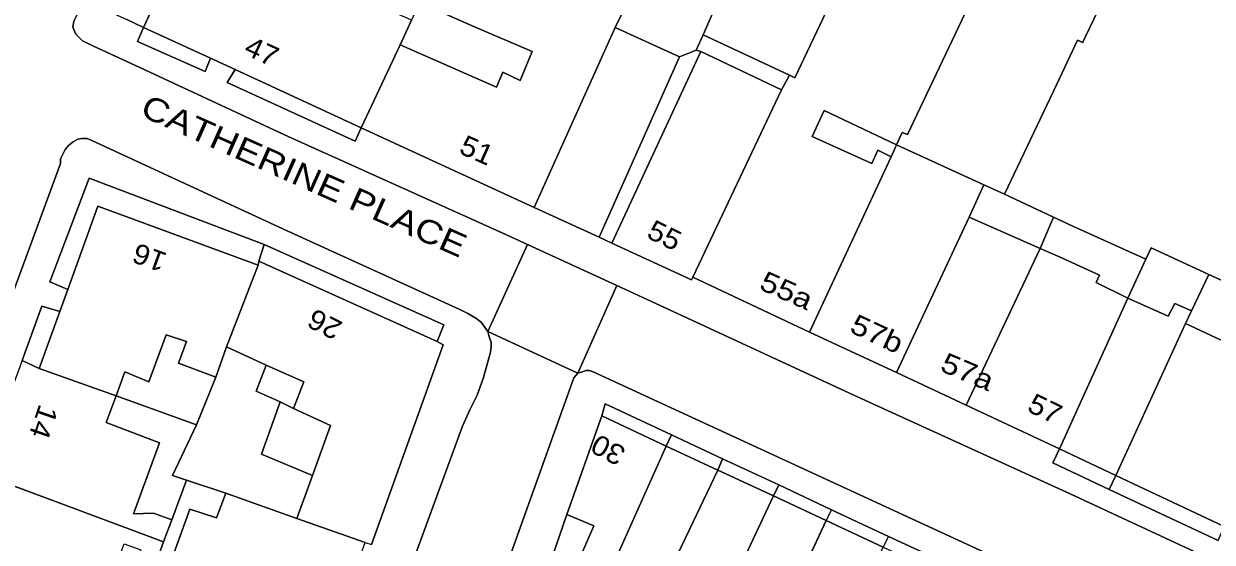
# Model space of a CAD drawing. Extents: x 528790 to 529292, y 179350 to 179856.
# Drawn here: x 529148.9 to 529237.6, y 179419.8 to 179458.5 of the extents above; entities that cross this region are included whole.
import ezdxf

# ---------------------------------------------------------------- set-up
doc = ezdxf.new("R2010")
doc.units = 0
doc.header["$LTSCALE"] = 0.6
doc.layers.add('1', color=7, linetype='Continuous', lineweight=13)
doc.layers.add('2', color=7, linetype='Continuous', lineweight=13)
doc.layers.add('5', color=7, linetype='Continuous')

msp = doc.modelspace()

# ---------------------------------------------------------------- linework, layer by layer
at = {"layer": '1'}
for points in [[(529203.704, 179467.191), (529210.6, 179482.95), (529209.35, 179483.45), (529205.4, 179484.95), (529199.95, 179473.2), (529198.94, 179470.979), (529201.672, 179469.755), (529199.962, 179465.94), (529197.23, 179467.164), (529196.947, 179466.532), (529195.7, 179463.85), (529193, 179458.25), (529197.8, 179456.05), (529199.05, 179456.55), (529199.55, 179457.7), (529201.924, 179463.125)], [(529218.5, 179480), (529210.6, 179482.95), (529203.704, 179467.191), (529209.252, 179464.762), (529207.472, 179460.696), (529201.924, 179463.125), (529199.55, 179457.7), (529206, 179454.7), (529206.4, 179454.5)], [(529223.465, 179467.493), (529224.55, 179469.75), (529227.4, 179475.9), (529221.2, 179478.75), (529218.5, 179480), (529206.4, 179454.5), (529206, 179454.7), (529205.4, 179453.6), (529198.8, 179439.6), (529207.5, 179435.5), (529213.6, 179448.6), (529212.6, 179449.1), (529212.15, 179448.1), (529207.7, 179450.1), (529208.6, 179452.05), (529214, 179449.5), (529214.4, 179450.4), (529214.8, 179450.25), (529219.8, 179460.8), (529220.2, 179460.7)], [(529157.8, 179458.25), (529161.45, 179466.1), (529164.55, 179472.75), (529165.2, 179474.3), (529160.8, 179476.3), (529160.65, 179475.95), (529155.75, 179465.25), (529153.4, 179460.25), (529156.55, 179458.85)], [(529229.655, 179460.856), (529234.9, 179472.4), (529232.55, 179473.5), (529229.4, 179474.9), (529227.4, 179475.9), (529224.55, 179469.75), (529223.465, 179467.493), (529220.2, 179460.7), (529219.8, 179460.8), (529214.8, 179450.25), (529214.4, 179450.4), (529214, 179449.5), (529220.5, 179446.5), (529222.05, 179445.8), (529225.703, 179453.506), (529226.15, 179454.45), (529227.5, 179457.3), (529227.887, 179457.117), (529227.929, 179457.205), (529228.098, 179457.563)], [(529195.7, 179463.85), (529191.02, 179466.027), (529189.25, 179466.85), (529187.829, 179463.891), (529187.184, 179462.499), (529187, 179462.1), (529180.6, 179465.05), (529178.371, 179460.076), (529180.398, 179459.204), (529182.5, 179458.3), (529186.8, 179456.45), (529185.9, 179454.3), (529184.6, 179454.9), (529184.15, 179453.8), (529179, 179456.05), (529176.939, 179456.951), (529174.05, 179450.75), (529186.95, 179444.8), (529193, 179458.25)], [(529177.8, 179458.8), (529161.45, 179466.1), (529157.8, 179458.25), (529162.8, 179455.95), (529164.65, 179455.1), (529174.05, 179450.75), (529176.939, 179456.951)], [(529186.8, 179456.45), (529182.5, 179458.3), (529180.398, 179459.204), (529178.371, 179460.076), (529177.8, 179458.8), (529176.939, 179456.951), (529179, 179456.05), (529184.15, 179453.8), (529184.6, 179454.9), (529185.9, 179454.3)], [(529157.8, 179458.25), (529157.35, 179457.2), (529162.4, 179454.95), (529162.8, 179455.95)], [(529191.8, 179442.6), (529197.8, 179456.05), (529193, 179458.25), (529186.95, 179444.8)], [(529205.4, 179453.6), (529206, 179454.7), (529199.55, 179457.7), (529199.05, 179456.55), (529199.4, 179456.45)], [(529199.4, 179456.45), (529199.05, 179456.55), (529197.8, 179456.05), (529191.8, 179442.6), (529192.75, 179442.15)], [(529199.4, 179456.45), (529192.75, 179442.15), (529198.7, 179439.4), (529198.8, 179439.6), (529205.4, 179453.6)], [(529164.65, 179455.1), (529164.05, 179454.15), (529173.6, 179449.75), (529174.05, 179450.75)], [(529213.6, 179448.6), (529214, 179449.5), (529208.6, 179452.05), (529207.7, 179450.1), (529212.15, 179448.1), (529212.6, 179449.1)], [(529207.5, 179435.5), (529214, 179432.5), (529219.4, 179444.1), (529220.5, 179446.5), (529214, 179449.5), (529213.6, 179448.6)], [(529166.35, 179440.5), (529166.4, 179440.8), (529166.8, 179442.05), (529153.75, 179447), (529150.8, 179439.25), (529152.15, 179438.7), (529154.4, 179444.9)], [(529224.7, 179441.75), (529225.7, 179444.1), (529222.05, 179445.8), (529220.5, 179446.5), (529219.4, 179444.1)], [(529152.15, 179438.7), (529151.55, 179437.05), (529150, 179432.8), (529155.75, 179430.75), (529156.4, 179432.55), (529158.2, 179431.8), (529159.5, 179435.3), (529161, 179434.8), (529160.4, 179433.2), (529163.2, 179432.15), (529164, 179434.4), (529166.35, 179440.5), (529154.4, 179444.9)], [(529219.4, 179444.1), (529214, 179432.5), (529219.2, 179430.05), (529224.7, 179441.75)], [(529232.6, 179440.95), (529227.2, 179443.4), (529225.7, 179444.1), (529224.7, 179441.75), (529226.2, 179441.1), (529229.15, 179439.75), (529228.9, 179439.2), (529231.25, 179438.05)], [(529166.8, 179442.05), (529166.4, 179440.8), (529179.7, 179434.8), (529180.2, 179436.05)], [(529186.46, 179442.05), (529183.5, 179435.55), (529190.2, 179432.45), (529193.12, 179438.98)], [(529231.25, 179438.05), (529228.9, 179439.2), (529229.15, 179439.75), (529226.2, 179441.1), (529224.7, 179441.75), (529219.2, 179430.05), (529226.15, 179426.8)], [(529237.3, 179439.8), (529233, 179441.8), (529232.6, 179440.95), (529231.25, 179438.05), (529234.25, 179436.7), (529234.75, 179437.65), (529236, 179437.1)], [(529174.35, 179419.8), (529174.8, 179419.65), (529180.15, 179434.55), (529179.7, 179434.8), (529166.4, 179440.8), (529166.35, 179440.5), (529164, 179434.4), (529166.95, 179433.05), (529169.75, 179431.8), (529169, 179429.8), (529171.75, 179428.55), (529170.4, 179424.8), (529169.25, 179421.6)], [(529245.4, 179436.1), (529237.3, 179439.8), (529236, 179437.1), (529235.55, 179436.15), (529241.25, 179433.5), (529243.663, 179432.378)], [(529190.2, 179432.45), (529190.55, 179432.55), (529190.8, 179432.65), (529191.05, 179432.65), (529191.35, 179432.55), (529242.05, 179409.15), (529242.35, 179408.85), (529242.6, 179408.15), (529250, 179413.05), (529240.8, 179417), (529226.95, 179423.45), (529210.8, 179430.8), (529195.7, 179437.8), (529193.12, 179438.98)], [(529226.15, 179426.8), (529230.35, 179424.8), (529235.55, 179436.15), (529236, 179437.1), (529234.75, 179437.65), (529234.25, 179436.7), (529231.25, 179438.05)], [(529150, 179432.8), (529151.55, 179437.05), (529150.2, 179437.45), (529148.75, 179433.4)], [(529242.6, 179430.1), (529243.663, 179432.378), (529241.25, 179433.5), (529235.55, 179436.15), (529230.35, 179424.8), (529238.45, 179421)], [(529161.75, 179428.6), (529163.2, 179432.15), (529160.4, 179433.2), (529161, 179434.8), (529159.5, 179435.3), (529158.2, 179431.8), (529156.4, 179432.55), (529155.75, 179430.75)], [(529163.2, 179432.15), (529161.75, 179428.6), (529159.95, 179424.8), (529161, 179424.45), (529163.95, 179423.5), (529169.25, 179421.6), (529170.4, 179424.8), (529166.6, 179426.4), (529168, 179430.3), (529166.2, 179431.1), (529166.95, 179433.05), (529164, 179434.4)], [(529159.9, 179421.5), (529158.55, 179422), (529157.05, 179421.95), (529159, 179427.25), (529155, 179428.75), (529155.75, 179430.75), (529150, 179432.8), (529148.75, 179433.4), (529145.6, 179424.95), (529159.3, 179419.85)], [(529168, 179430.3), (529169, 179429.8), (529169.75, 179431.8), (529166.95, 179433.05), (529166.2, 179431.1)], [(529159.9, 179421.5), (529161, 179424.45), (529159.95, 179424.8), (529161.75, 179428.6), (529155.75, 179430.75), (529155, 179428.75), (529159, 179427.25), (529157.05, 179421.95), (529158.55, 179422)], [(529169, 179429.8), (529168, 179430.3), (529166.6, 179426.4), (529170.4, 179424.8), (529171.75, 179428.55)], [(529196.8, 179427), (529197.2, 179427.85), (529192.25, 179430.15), (529192, 179429.25)], [(529192.8, 179418.05), (529196.8, 179427), (529192, 179429.25), (529189.4, 179421.9), (529191.4, 179421.05), (529190.55, 179419.1)], [(529201, 179426.05), (529197.2, 179427.85), (529196.8, 179427), (529200.65, 179425.2)], [(529192.6, 179417.75), (529196.35, 179416.05), (529197.75, 179419.1), (529200.65, 179425.2), (529196.8, 179427), (529192.8, 179418.05)], [(529200.65, 179425.2), (529204.8, 179423.3), (529205.2, 179424.1), (529201, 179426.05)], [(529230.35, 179424.8), (529226.15, 179426.8), (529225.65, 179425.75), (529229.85, 179423.75)], [(529201.95, 179417.2), (529204.8, 179423.3), (529200.65, 179425.2), (529197.75, 179419.1)], [(529154, 179405.35), (529154.8, 179407.55), (529152.2, 179408.5), (529156.35, 179419.7), (529157.6, 179419.25), (529157.4, 179418.65), (529158.7, 179418.2), (529159.3, 179419.85), (529145.6, 179424.95), (529144.8, 179422.75), (529144.15, 179421), (529142.4, 179416.4), (529143.2, 179416.1), (529140.9, 179409.8), (529151.2, 179405.95), (529153.9, 179405)], [(529158.7, 179418.2), (529157.9, 179416.1), (529159, 179415.75), (529160.8, 179415.1), (529161.6, 179417.1), (529160.2, 179417.55), (529160.6, 179418.5), (529159.95, 179418.7), (529161.25, 179422.3), (529163.25, 179421.65), (529163.95, 179423.5), (529161, 179424.45), (529159.9, 179421.5), (529159.3, 179419.85)], [(529238, 179419.95), (529238.45, 179421), (529230.35, 179424.8), (529229.85, 179423.75)], [(529172.15, 179413.75), (529174.35, 179419.8), (529169.25, 179421.6), (529163.95, 179423.5), (529163.25, 179421.65), (529161.25, 179422.3), (529159.95, 179418.7), (529160.6, 179418.5), (529160.2, 179417.55), (529161.6, 179417.1), (529160.8, 179415.1), (529171.2, 179411.3)], [(529209.15, 179422.25), (529205.2, 179424.1), (529204.8, 179423.3), (529208.75, 179421.45)], [(529208.75, 179421.45), (529204.8, 179423.3), (529201.95, 179417.2), (529200.4, 179413.7), (529202.75, 179412.65), (529201.4, 179409.8), (529203, 179409.1), (529204.2, 179411.7)], [(529191.45, 179415.1), (529192.6, 179417.75), (529192.8, 179418.05), (529190.55, 179419.1), (529191.4, 179421.05), (529189.4, 179421.9), (529187.55, 179416.55), (529187, 179415.05), (529190.8, 179413.7)], [(529208.75, 179421.45), (529213, 179419.45), (529213.4, 179420.25), (529209.15, 179422.25)], [(529204.2, 179411.7), (529208.6, 179409.7), (529213, 179419.45), (529208.75, 179421.45)], [(529213.4, 179420.25), (529213, 179419.45), (529217.15, 179417.55), (529217.5, 179418.35)]]:
    msp.add_lwpolyline(points, close=True, dxfattribs=at)
for points in [[(529229.655, 179460.856), (529228.098, 179457.563), (529227.929, 179457.205), (529227.887, 179457.117), (529227.5, 179457.3), (529226.15, 179454.45), (529225.703, 179453.506), (529222.05, 179445.8), (529225.7, 179444.1), (529227.2, 179443.4), (529232.6, 179440.95), (529233, 179441.8), (529237.3, 179439.8), (529245.4, 179436.1), (529246.7, 179435.5), (529249.795, 179441.859), (529253.448, 179449.363), (529254.218, 179450.942), (529255.002, 179452.549), (529259, 179460.75)], [(529129.6, 179388.25), (529151.6, 179448.1), (529151.6, 179448.45), (529151.95, 179449.15), (529152.2, 179449.45), (529152.55, 179449.7), (529152.9, 179449.9), (529153.2, 179449.95), (529153.6, 179449.95), (529153.95, 179449.8), (529168.25, 179443.2), (529181.4, 179437.2), (529182, 179436.9), (529182.6, 179436.55), (529183, 179436.25), (529183.5, 179435.55), (529186.46, 179442.05), (529184.6, 179442.9), (529168.6, 179450.1), (529157.2, 179455.4), (529154.075, 179456.846), (529153.247, 179457.24), (529152.737, 179457.756), (529152.53, 179458.27), (529152.592, 179458.708)], [(529152.592, 179458.708), (529152.53, 179458.27), (529152.737, 179457.756), (529153.247, 179457.24), (529154.075, 179456.846), (529157.2, 179455.4), (529168.6, 179450.1), (529184.6, 179442.9), (529186.46, 179442.05), (529193.12, 179438.98), (529195.7, 179437.8), (529210.8, 179430.8), (529226.95, 179423.45), (529240.8, 179417)], [(529238, 179419.95), (529229.85, 179423.75), (529225.65, 179425.75), (529226.15, 179426.8), (529219.2, 179430.05), (529214, 179432.5), (529207.5, 179435.5), (529198.8, 179439.6), (529198.7, 179439.4), (529192.75, 179442.15), (529191.8, 179442.6), (529186.95, 179444.8), (529174.05, 179450.75), (529173.6, 179449.75), (529164.05, 179454.15), (529164.65, 179455.1), (529162.8, 179455.95), (529162.4, 179454.95), (529157.35, 179457.2), (529157.8, 179458.25), (529156.55, 179458.85)], [(529176.4, 179414.3), (529181.6, 179428.5), (529182.15, 179429.7), (529182.7, 179430.8), (529183.15, 179432.05), (529183.5, 179433.3), (529183.7, 179434), (529183.75, 179434.4), (529183.75, 179434.75), (529183.6, 179435.15), (529183.5, 179435.55), (529183, 179436.25), (529182.6, 179436.55), (529182, 179436.9), (529181.4, 179437.2), (529168.25, 179443.2), (529153.95, 179449.8), (529153.6, 179449.95), (529153.2, 179449.95), (529152.9, 179449.9), (529152.55, 179449.7), (529152.2, 179449.45), (529151.95, 179449.15), (529151.6, 179448.45), (529151.6, 179448.1), (529129.6, 179388.25)], [(529148.75, 179433.4), (529150.2, 179437.45), (529151.55, 179437.05), (529152.15, 179438.7), (529150.8, 179439.25), (529153.75, 179447), (529166.8, 179442.05), (529180.2, 179436.05), (529179.7, 179434.8), (529180.15, 179434.55), (529174.8, 179419.65)], [(529169.205, 179374.273), (529189.9, 179432.1), (529190.2, 179432.45), (529183.5, 179435.55), (529183.6, 179435.15), (529183.75, 179434.75), (529183.75, 179434.4), (529183.7, 179434), (529183.5, 179433.3), (529183.15, 179432.05), (529182.7, 179430.8), (529182.15, 179429.7), (529181.6, 179428.5), (529176.4, 179414.3)], [(529242.05, 179409.15), (529191.35, 179432.55), (529191.05, 179432.65), (529190.8, 179432.65), (529190.55, 179432.55), (529190.2, 179432.45), (529189.9, 179432.1), (529169.205, 179374.273)], [(529187.55, 179416.55), (529189.4, 179421.9), (529192, 179429.25), (529192.25, 179430.15), (529197.2, 179427.85), (529201, 179426.05), (529205.2, 179424.1), (529209.15, 179422.25), (529213.4, 179420.25), (529217.5, 179418.35)]]:
    msp.add_lwpolyline(points, dxfattribs=at)
at = {"layer": '2'}
for p, q in [((529161.45, 179466.1), (529157.8, 179458.25)), ((529195.7, 179463.85), (529193, 179458.25)), ((529201.924, 179463.125), (529199.55, 179457.7)), ((529157.8, 179458.25), (529162.8, 179455.95)), ((529177.8, 179458.8), (529176.939, 179456.951)), ((529186.95, 179444.8), (529193, 179458.25)), ((529193, 179458.25), (529197.8, 179456.05)), ((529199.55, 179457.7), (529199.05, 179456.55)), ((529206, 179454.7), (529199.55, 179457.7)), ((529174.05, 179450.75), (529176.939, 179456.951)), ((529192.75, 179442.15), (529199.4, 179456.45)), ((529199.05, 179456.55), (529197.8, 179456.05)), ((529199.05, 179456.55), (529199.4, 179456.45)), ((529199.4, 179456.45), (529205.4, 179453.6)), ((529162.8, 179455.95), (529164.65, 179455.1)), ((529197.8, 179456.05), (529191.8, 179442.6)), ((529164.65, 179455.1), (529174.05, 179450.75)), ((529205.4, 179453.6), (529206, 179454.7)), ((529205.4, 179453.6), (529198.8, 179439.6)), ((529174.05, 179450.75), (529186.95, 179444.8)), ((529213.6, 179448.6), (529214, 179449.5)), ((529214, 179449.5), (529220.5, 179446.5)), ((529207.5, 179435.5), (529213.6, 179448.6)), ((529220.5, 179446.5), (529219.4, 179444.1)), ((529222.05, 179445.8), (529220.5, 179446.5)), ((529222.05, 179445.8), (529225.7, 179444.1)), ((529186.95, 179444.8), (529191.8, 179442.6)), ((529219.4, 179444.1), (529214, 179432.5)), ((529219.4, 179444.1), (529224.7, 179441.75)), ((529224.7, 179441.75), (529225.7, 179444.1)), ((529166.8, 179442.05), (529166.4, 179440.8)), ((529183.5, 179435.55), (529186.46, 179442.05)), ((529193.12, 179438.98), (529186.46, 179442.05)), ((529191.8, 179442.6), (529192.75, 179442.15)), ((529224.7, 179441.75), (529219.2, 179430.05)), ((529166.35, 179440.5), (529164, 179434.4)), ((529166.35, 179440.5), (529166.4, 179440.8)), ((529166.4, 179440.8), (529179.7, 179434.8)), ((529232.6, 179440.95), (529231.25, 179438.05)), ((529198.8, 179439.6), (529207.5, 179435.5)), ((529236, 179437.1), (529237.3, 179439.8)), ((529237.3, 179439.8), (529245.4, 179436.1)), ((529151.55, 179437.05), (529152.15, 179438.7)), ((529190.2, 179432.45), (529193.12, 179438.98)), ((529231.25, 179438.05), (529226.15, 179426.8)), ((529150, 179432.8), (529151.55, 179437.05)), ((529236, 179437.1), (529235.55, 179436.15)), ((529235.55, 179436.15), (529230.35, 179424.8)), ((529183.5, 179435.55), (529190.2, 179432.45)), ((529207.5, 179435.5), (529214, 179432.5)), ((529164, 179434.4), (529163.2, 179432.15)), ((529166.95, 179433.05), (529164, 179434.4)), ((529148.75, 179433.4), (529150, 179432.8)), ((529150, 179432.8), (529155.75, 179430.75)), ((529214, 179432.5), (529219.2, 179430.05)), ((529163.2, 179432.15), (529161.75, 179428.6)), ((529155.75, 179430.75), (529161.75, 179428.6)), ((529168, 179430.3), (529169, 179429.8)), ((529219.2, 179430.05), (529226.15, 179426.8)), ((529192, 179429.25), (529189.4, 179421.9)), ((529192, 179429.25), (529196.8, 179427)), ((529197.2, 179427.85), (529196.8, 179427)), ((529201, 179426.05), (529197.2, 179427.85)), ((529196.8, 179427), (529192.8, 179418.05)), ((529196.8, 179427), (529200.65, 179425.2)), ((529201, 179426.05), (529200.65, 179425.2)), ((529205.2, 179424.1), (529201, 179426.05)), ((529226.15, 179426.8), (529230.35, 179424.8)), ((529200.65, 179425.2), (529197.75, 179419.1)), ((529200.65, 179425.2), (529204.8, 179423.3)), ((529159.3, 179419.85), (529145.6, 179424.95)), ((529161, 179424.45), (529159.9, 179421.5)), ((529161, 179424.45), (529163.95, 179423.5)), ((529169.25, 179421.6), (529170.4, 179424.8)), ((529230.35, 179424.8), (529229.85, 179423.75)), ((529230.35, 179424.8), (529238.45, 179421)), ((529169.25, 179421.6), (529163.95, 179423.5)), ((529205.2, 179424.1), (529204.8, 179423.3)), ((529209.15, 179422.25), (529205.2, 179424.1)), ((529229.85, 179423.75), (529238, 179419.95)), ((529204.8, 179423.3), (529201.95, 179417.2)), ((529204.8, 179423.3), (529208.75, 179421.45)), ((529209.15, 179422.25), (529208.75, 179421.45)), ((529213.4, 179420.25), (529209.15, 179422.25)), ((529159.9, 179421.5), (529159.3, 179419.85)), ((529174.35, 179419.8), (529169.25, 179421.6)), ((529208.75, 179421.45), (529204.2, 179411.7)), ((529208.75, 179421.45), (529213, 179419.45)), ((529159.3, 179419.85), (529158.7, 179418.2)), ((529213.4, 179420.25), (529213, 179419.45)), ((529217.5, 179418.35), (529213.4, 179420.25))]:
    msp.add_line(p, q, dxfattribs=at)
for points in [[(529218.5, 179480), (529206.4, 179454.5), (529206, 179454.7)], [(529227.4, 179475.9), (529224.55, 179469.75), (529223.465, 179467.493), (529220.2, 179460.7), (529219.8, 179460.8), (529214.8, 179450.25), (529214.4, 179450.4), (529214, 179449.5)], [(529234.9, 179472.4), (529229.655, 179460.856), (529228.098, 179457.563), (529227.929, 179457.205), (529227.887, 179457.117), (529227.5, 179457.3), (529226.15, 179454.45), (529225.703, 179453.506), (529222.05, 179445.8)], [(529186.46, 179442.05), (529184.6, 179442.9), (529168.6, 179450.1), (529157.2, 179455.4), (529154.075, 179456.846), (529153.247, 179457.24), (529152.737, 179457.756), (529152.53, 179458.27), (529152.592, 179458.708), (529153.168, 179459.806), (529153.4, 179460.25)], [(529153.4, 179460.25), (529156.55, 179458.85), (529157.8, 179458.25)], [(529176.939, 179456.951), (529179, 179456.05), (529184.15, 179453.8), (529184.6, 179454.9), (529185.9, 179454.3), (529186.8, 179456.45), (529182.5, 179458.3), (529180.398, 179459.204), (529178.371, 179460.076)], [(529162.8, 179455.95), (529162.4, 179454.95), (529157.35, 179457.2), (529157.8, 179458.25)], [(529174.05, 179450.75), (529173.6, 179449.75), (529164.05, 179454.15), (529164.65, 179455.1)], [(529214, 179449.5), (529208.6, 179452.05), (529207.7, 179450.1), (529212.15, 179448.1), (529212.6, 179449.1), (529213.6, 179448.6)], [(529129.75, 179387.2), (529129.6, 179387.45), (529129.55, 179387.75), (529129.55, 179388), (529129.6, 179388.25), (529151.6, 179448.1), (529151.6, 179448.45), (529151.95, 179449.15), (529152.2, 179449.45), (529152.55, 179449.7), (529152.9, 179449.9), (529153.2, 179449.95), (529153.6, 179449.95), (529153.95, 179449.8), (529168.25, 179443.2), (529181.4, 179437.2), (529182, 179436.9), (529182.6, 179436.55), (529183, 179436.25), (529183.5, 179435.55)], [(529166.8, 179442.05), (529153.75, 179447), (529150.8, 179439.25), (529152.15, 179438.7)], [(529152.15, 179438.7), (529154.4, 179444.9), (529166.35, 179440.5)], [(529225.7, 179444.1), (529227.2, 179443.4), (529232.6, 179440.95)], [(529166.8, 179442.05), (529180.2, 179436.05), (529179.7, 179434.8)], [(529192.75, 179442.15), (529198.7, 179439.4), (529198.8, 179439.6)], [(529224.7, 179441.75), (529226.2, 179441.1), (529229.15, 179439.75), (529228.9, 179439.2), (529231.25, 179438.05)], [(529232.6, 179440.95), (529233, 179441.8), (529237.3, 179439.8)], [(529250, 179413.05), (529240.8, 179417), (529226.95, 179423.45), (529210.8, 179430.8), (529195.7, 179437.8), (529193.12, 179438.98)], [(529231.25, 179438.05), (529234.25, 179436.7), (529234.75, 179437.65), (529236, 179437.1)], [(529151.55, 179437.05), (529150.2, 179437.45), (529148.75, 179433.4)], [(529235.55, 179436.15), (529241.25, 179433.5), (529243.663, 179432.378)], [(529163.2, 179432.15), (529160.4, 179433.2), (529161, 179434.8), (529159.5, 179435.3), (529158.2, 179431.8), (529156.4, 179432.55), (529155.75, 179430.75)], [(529161.25, 179375.45), (529161.6, 179375.55), (529161.9, 179375.7), (529162.05, 179375.9), (529162.35, 179376.4), (529167.35, 179390.15), (529171.5, 179401.3), (529176.4, 179414.3), (529181.6, 179428.5), (529182.15, 179429.7), (529182.7, 179430.8), (529183.15, 179432.05), (529183.5, 179433.3), (529183.7, 179434), (529183.75, 179434.4), (529183.75, 179434.75), (529183.6, 179435.15), (529183.5, 179435.55)], [(529179.7, 179434.8), (529180.15, 179434.55), (529174.8, 179419.65)], [(529168, 179430.3), (529166.2, 179431.1), (529166.95, 179433.05)], [(529169, 179429.8), (529169.75, 179431.8), (529166.95, 179433.05)], [(529190.2, 179432.45), (529189.9, 179432.1), (529169.205, 179374.273), (529169.204, 179374.262), (529169.2, 179374.196), (529169.131, 179373.129), (529169.129, 179373.091), (529169.121, 179373.036), (529169.115, 179372.981)], [(529242.6, 179408.15), (529242.35, 179408.85), (529242.05, 179409.15), (529191.35, 179432.55), (529191.05, 179432.65), (529190.8, 179432.65), (529190.55, 179432.55), (529190.2, 179432.45)], [(529155.75, 179430.75), (529155, 179428.75), (529159, 179427.25), (529157.05, 179421.95), (529158.55, 179422), (529159.9, 179421.5)], [(529170.4, 179424.8), (529166.6, 179426.4), (529168, 179430.3)], [(529170.4, 179424.8), (529171.75, 179428.55), (529169, 179429.8)], [(529197.2, 179427.85), (529192.25, 179430.15), (529192, 179429.25)], [(529161.75, 179428.6), (529159.95, 179424.8), (529161, 179424.45)], [(529229.85, 179423.75), (529225.65, 179425.75), (529226.15, 179426.8)], [(529163.95, 179423.5), (529163.25, 179421.65), (529161.25, 179422.3), (529159.95, 179418.7), (529160.6, 179418.5), (529160.2, 179417.55), (529161.6, 179417.1), (529160.8, 179415.1)], [(529189.4, 179421.9), (529187.55, 179416.55), (529187, 179415.05)], [(529189.4, 179421.9), (529191.4, 179421.05), (529190.55, 179419.1), (529192.8, 179418.05)]]:
    msp.add_lwpolyline(points, dxfattribs=at)

# ---------------------------------------------------------------- texts
at = {"layer": '5'}
for s, height, rotation, width, p in [('47', 1.5, 335, 1.1, (529165.2, 179456.3)), ('CATHERINE PLACE', 1.75, 336, 1.2, (529157.45, 179451.7)), ('51', 1.5, 336, 1.1, (529181.25, 179448.9)), ('55', 1.5, 334, 1.1, (529195.25, 179442.6)), ('16', 1.5, 160, 1.1, (529159.65, 179441.35)), ('55a', 1.5, 336, 1.2, (529203.65, 179438.75)), ('26', 1.5, 153, 1.1, (529172.75, 179436.2)), ('57b', 1.5, 335, 1.2, (529210.4, 179435.55)), ('57a', 1.5, 337, 1.2, (529217.15, 179432.65)), ('57', 1.5, 334, 1.1, (529223.65, 179429.65)), ('14', 1.5, 251, 1.1, (529150.04, 179430.21)), ('30', 1.5, 152, 1.1, (529193.9, 179426.8))]:
    msp.add_text(s, height=height, rotation=rotation, dxfattribs=dict(at, width=width)).set_placement(p)

doc.saveas('drawing.dxf')
